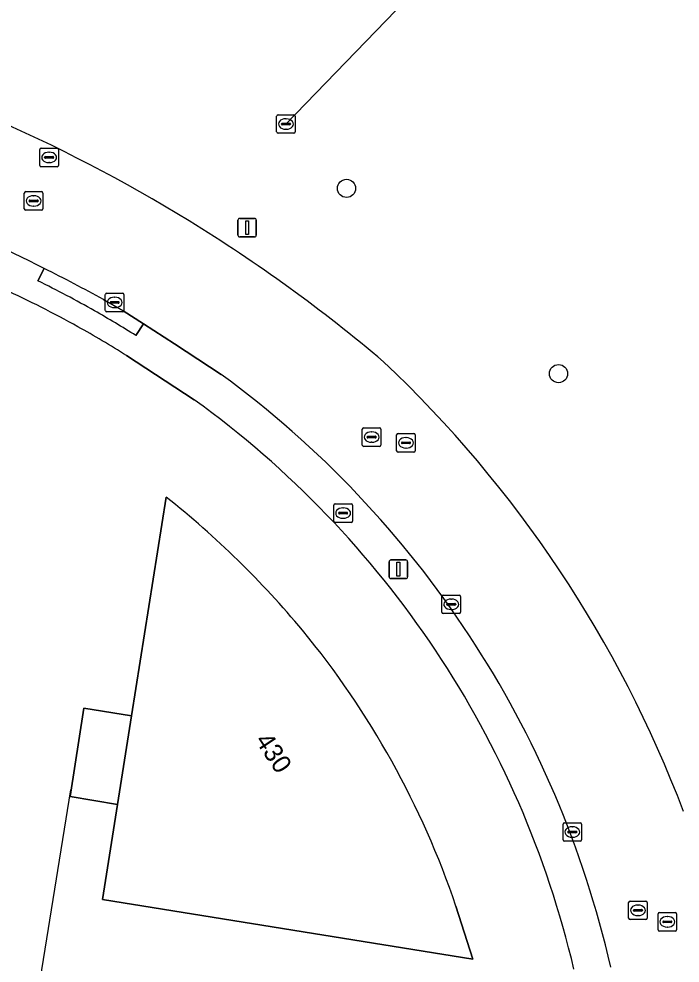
# Model space of a CAD drawing. Extents: x 154324 to 155744, y 382937 to 384188.
# Drawn here: x 155347.8 to 155383.3, y 383421.7 to 383472.5 of the extents above; entities that cross this region are included whole.
import ezdxf

# ---------------------------------------------------------------- set-up
doc = ezdxf.new("R2010")
doc.units = 0
for name, color, linetype in [('IMGEO_Boom', 7, 'Continuous'), ('IMGEO_Brandkraan', 7, 'Continuous'), ('IMGEO_Duiker', 7, 'Continuous'), ('IMGEO_Erf', 7, 'Continuous'), ('IMGEO_Groenvoorziening', 7, 'Continuous'), ('IMGEO_Hek', 7, 'Continuous'), ('IMGEO_Kolk', 7, 'Continuous'), ('IMGEO_Lichtmast', 7, 'Continuous'), ('IMGEO_Pand', 7, 'Continuous'), ('IMGEO_Pand_nummerreeks', 7, 'Continuous'), ('IMGEO_Rijbaan_lokaal_open', 7, 'Continuous'), ('IMGEO_Rioolput', 7, 'Continuous'), ('IMGEO_Voetpad_open', 7, 'Continuous')]:
    doc.layers.add(name, color=color, linetype=linetype)

msp = doc.modelspace()

# ---------------------------------------------------------------- linework, layer by layer
at = {"layer": 'IMGEO_Boom'}
for centre in [(155365.404, 383463.411), (155376.801, 383453.45)]:
    msp.add_circle(centre, 0.489, dxfattribs=at)
at = {"layer": 'IMGEO_Brandkraan'}
for p, q in [((155364.796, 383446.444), (155365.648, 383446.444)), ((155364.721, 383445.518), (155364.721, 383446.37)), ((155364.98, 383445.938), (155364.98, 383445.95)), ((155365.023, 383445.987), (155365.421, 383445.987)), ((155365.209, 383446.224), (155365.234, 383446.224)), ((155365.464, 383445.95), (155365.464, 383445.938)), ((155365.722, 383446.37), (155365.722, 383445.518)), ((155365.648, 383445.444), (155364.796, 383445.444)), ((155365.418, 383445.901), (155365.02, 383445.901)), ((155365.232, 383445.664), (155365.207, 383445.664))]:
    msp.add_line(p, q, dxfattribs=at)
for points in [[(155364.796, 383446.444), (155365.648, 383446.444)], [(155364.721, 383445.518), (155364.721, 383446.37)], [(155365.722, 383446.37), (155365.722, 383445.518)], [(155365.648, 383445.444), (155364.796, 383445.444)]]:
    msp.add_lwpolyline(points, dxfattribs=at)
for centre, radius, start, end in [((155364.798, 383446.368), 0.0765, 91.552, 178.448), ((155364.798, 383446.368), 0.0765, 91.552, 178.448), ((155365.646, 383446.368), 0.0765, 1.552, 88.448), ((155365.646, 383446.368), 0.0765, 1.552, 88.448), ((155365.02, 383445.947), 0.0403, 85.8775, 175.7526), ((155365.017, 383445.937), 0.0366, 178.938, 274.7102), ((155365.421, 383445.944), 0.043, 264.8664, 352.4533), ((155365.425, 383445.949), 0.0386, 1.7309, 96.639), ((155364.798, 383445.52), 0.0765, 181.552, 268.448), ((155364.798, 383445.52), 0.0765, 181.552, 268.448), ((155365.646, 383445.52), 0.0765, 271.552, 358.448), ((155365.646, 383445.52), 0.0765, 271.552, 358.448)]:
    msp.add_arc(centre, radius, start, end, dxfattribs=at)
for centre, major_axis, ratio, start_param, end_param in [((155365.208, 383445.944), (-0.387, 0.002), 0.722429, 4.712389, 7.853982), ((155365.233, 383445.944), (-0.39, 0.002), 0.717154, 1.570796, 4.712389)]:
    msp.add_ellipse(centre, major_axis=major_axis, ratio=ratio, start_param=start_param, end_param=end_param, dxfattribs=at)
at = {"layer": 'IMGEO_Duiker'}
msp.add_lwpolyline([(155362.15, 383466.875), (155370.748, 383475.778)], dxfattribs=at)
at = {"layer": 'IMGEO_Erf'}
for points in [[(155357.216, 383452.045), (155353.569, 383454.42)], [(155352.285, 383425.153), (155353.096, 383430.27), (155350.549, 383430.699), (155351.285, 383435.448), (155353.852, 383435.041), (155355.715, 383446.803)], [(155371.286, 383424.798), (155372.19, 383421.959), (155352.285, 383425.153)]]:
    msp.add_lwpolyline(points, dxfattribs=at)
for centre, radius, start, end in [((155325.371, 383410.082), 52.545, 60.8513, 65.7078), ((155325.24, 383409.862), 52.801, 57.5525, 60.844), ((155326.36, 383409.367), 52.663, 13.2166, 54.1334), ((155325.018, 383408.09), 49.406, 39.6858, 51.5876), ((155326.8, 383409.792), 46.949, 18.6408, 39.4769)]:
    msp.add_arc(centre, radius, start, end, dxfattribs=at)
at = {"layer": 'IMGEO_Groenvoorziening'}
for centre, radius, start, end in [((155312.033, 383388.632), 85.735, 58.41362, 74.83277), ((155311.996, 383388.605), 85.777, 49.76722, 58.40243), ((155322.678, 383406.824), 65.069, 20.763, 46.58434)]:
    msp.add_arc(centre, radius, start, end, dxfattribs=at)
at = {"layer": 'IMGEO_Hek'}
msp.add_lwpolyline([(155353.397, 383415.758), (155348.254, 383416.592), (155350.587, 383431.051)], dxfattribs=at)
at = {"layer": 'IMGEO_Kolk'}
for p, q in [((155352.439, 383456.851), (155352.439, 383457.703)), ((155352.514, 383457.777), (155353.366, 383457.777)), ((155353.44, 383457.703), (155353.44, 383456.851)), ((155352.698, 383457.271), (155352.698, 383457.283)), ((155353.136, 383457.234), (155352.738, 383457.234)), ((155352.741, 383457.32), (155353.139, 383457.32)), ((155352.927, 383457.557), (155352.952, 383457.557)), ((155353.182, 383457.283), (155353.182, 383457.271)), ((155353.366, 383456.777), (155352.514, 383456.777)), ((155352.95, 383456.997), (155352.925, 383456.997)), ((155370.531, 383440.613), (155370.531, 383441.465)), ((155370.606, 383441.539), (155371.458, 383441.539)), ((155371.532, 383441.465), (155371.532, 383440.613)), ((155370.79, 383441.033), (155370.79, 383441.045)), ((155371.228, 383440.996), (155370.83, 383440.996)), ((155370.833, 383441.082), (155371.231, 383441.082)), ((155371.019, 383441.319), (155371.044, 383441.319)), ((155371.274, 383441.045), (155371.274, 383441.033)), ((155371.458, 383440.539), (155370.606, 383440.539)), ((155371.042, 383440.759), (155371.017, 383440.759)), ((155377.041, 383428.365), (155377.041, 383429.217)), ((155377.116, 383429.291), (155377.968, 383429.291)), ((155378.042, 383429.217), (155378.042, 383428.365)), ((155377.3, 383428.785), (155377.3, 383428.797)), ((155377.738, 383428.748), (155377.34, 383428.748)), ((155377.343, 383428.834), (155377.741, 383428.834)), ((155377.529, 383429.071), (155377.554, 383429.071)), ((155377.784, 383428.797), (155377.784, 383428.785)), ((155377.968, 383428.291), (155377.116, 383428.291)), ((155377.552, 383428.511), (155377.527, 383428.511))]:
    msp.add_line(p, q, dxfattribs=at)
for points in [[(155352.439, 383456.851), (155352.439, 383457.703)], [(155352.514, 383457.777), (155353.366, 383457.777)], [(155353.44, 383457.703), (155353.44, 383456.851)], [(155353.366, 383456.777), (155352.514, 383456.777)], [(155370.531, 383440.613), (155370.531, 383441.465)], [(155370.606, 383441.539), (155371.458, 383441.539)], [(155371.532, 383441.465), (155371.532, 383440.613)], [(155371.458, 383440.539), (155370.606, 383440.539)], [(155377.041, 383428.365), (155377.041, 383429.217)], [(155377.116, 383429.291), (155377.968, 383429.291)], [(155378.042, 383429.217), (155378.042, 383428.365)], [(155377.968, 383428.291), (155377.116, 383428.291)]]:
    msp.add_lwpolyline(points, dxfattribs=at)
for centre, radius, start, end in [((155352.516, 383457.701), 0.0765, 91.552, 178.448), ((155352.516, 383457.701), 0.0765, 91.552, 178.448), ((155353.364, 383457.701), 0.0765, 1.552, 88.448), ((155353.364, 383457.701), 0.0765, 1.552, 88.448), ((155352.738, 383457.28), 0.0403, 85.8775, 175.7526), ((155352.735, 383457.27), 0.0366, 178.938, 274.7102), ((155353.139, 383457.277), 0.043, 264.8664, 352.4533), ((155353.143, 383457.282), 0.0386, 1.7309, 96.639), ((155352.516, 383456.853), 0.0765, 181.552, 268.448), ((155352.516, 383456.853), 0.0765, 181.552, 268.448), ((155353.364, 383456.853), 0.0765, 271.552, 358.448), ((155353.364, 383456.853), 0.0765, 271.552, 358.448), ((155370.608, 383441.463), 0.0765, 91.552, 178.448), ((155370.608, 383441.463), 0.0765, 91.552, 178.448), ((155371.456, 383441.463), 0.0765, 1.552, 88.448), ((155371.456, 383441.463), 0.0765, 1.552, 88.448), ((155370.83, 383441.042), 0.0403, 85.8775, 175.7526), ((155370.827, 383441.032), 0.0366, 178.938, 274.7102), ((155371.231, 383441.039), 0.043, 264.8664, 352.4533), ((155371.235, 383441.044), 0.0386, 1.7309, 96.639), ((155370.608, 383440.615), 0.0765, 181.552, 268.448), ((155370.608, 383440.615), 0.0765, 181.552, 268.448), ((155371.456, 383440.615), 0.0765, 271.552, 358.448), ((155371.456, 383440.615), 0.0765, 271.552, 358.448), ((155377.118, 383429.215), 0.0765, 91.552, 178.448), ((155377.118, 383429.215), 0.0765, 91.552, 178.448), ((155377.966, 383429.215), 0.0765, 1.552, 88.448), ((155377.966, 383429.215), 0.0765, 1.552, 88.448), ((155377.34, 383428.794), 0.0403, 85.8775, 175.7526), ((155377.337, 383428.784), 0.0366, 178.938, 274.7102), ((155377.741, 383428.791), 0.043, 264.8664, 352.4533), ((155377.745, 383428.796), 0.0386, 1.7309, 96.639), ((155377.118, 383428.367), 0.0765, 181.552, 268.448), ((155377.118, 383428.367), 0.0765, 181.552, 268.448), ((155377.966, 383428.367), 0.0765, 271.552, 358.448), ((155377.966, 383428.367), 0.0765, 271.552, 358.448)]:
    msp.add_arc(centre, radius, start, end, dxfattribs=at)
for centre, major_axis, ratio, start_param, end_param in [((155352.926, 383457.277), (-0.387, 0.002), 0.722429, 4.712389, 7.853982), ((155352.951, 383457.277), (-0.39, 0.002), 0.717154, 1.570796, 4.712389), ((155371.018, 383441.039), (-0.387, 0.002), 0.722429, 4.712389, 7.853982), ((155371.043, 383441.039), (-0.39, 0.002), 0.717154, 1.570796, 4.712389), ((155377.528, 383428.791), (-0.387, 0.002), 0.722429, 4.712389, 7.853982), ((155377.553, 383428.791), (-0.39, 0.002), 0.717154, 1.570796, 4.712389)]:
    msp.add_ellipse(centre, major_axis=major_axis, ratio=ratio, start_param=start_param, end_param=end_param, dxfattribs=at)
at = {"layer": 'IMGEO_Lichtmast'}
for p, q in [((155359.563, 383460.901), (155359.563, 383461.701)), ((155359.563, 383461.701), (155359.563, 383460.901)), ((155359.663, 383461.801), (155360.453, 383461.801)), ((155360.453, 383461.801), (155359.663, 383461.801)), ((155360.553, 383461.701), (155360.553, 383460.901)), ((155360.553, 383460.901), (155360.553, 383461.701)), ((155360.453, 383460.801), (155359.663, 383460.801)), ((155359.663, 383460.801), (155360.453, 383460.801)), ((155367.795, 383443.423), (155368.585, 383443.423)), ((155368.585, 383443.423), (155367.795, 383443.423)), ((155367.695, 383442.523), (155367.695, 383443.323)), ((155367.695, 383443.323), (155367.695, 383442.523)), ((155368.685, 383443.323), (155368.685, 383442.523)), ((155368.685, 383442.523), (155368.685, 383443.323)), ((155368.585, 383442.423), (155367.795, 383442.423)), ((155367.795, 383442.423), (155368.585, 383442.423))]:
    msp.add_line(p, q, dxfattribs=at)
for points in [[(155359.983, 383461.676), (155360.133, 383461.676), (155360.133, 383460.926), (155359.983, 383460.926), (155359.983, 383461.676)], [(155368.115, 383443.298), (155368.265, 383443.298), (155368.265, 383442.548), (155368.115, 383442.548), (155368.115, 383443.298)]]:
    msp.add_lwpolyline(points, dxfattribs=at)
for centre, start, end in [((155359.663, 383461.701), 90, 180), ((155359.663, 383461.701), 90, 180), ((155360.453, 383461.701), 0, 90), ((155360.453, 383461.701), 360, 90), ((155359.663, 383460.901), 180, 270), ((155359.663, 383460.901), 180, 270), ((155360.453, 383460.901), 270, 0), ((155360.453, 383460.901), 270, 0), ((155367.795, 383443.323), 90, 180), ((155367.795, 383443.323), 90, 180), ((155368.585, 383443.323), 0, 90), ((155368.585, 383443.323), 360, 90), ((155367.795, 383442.523), 180, 270), ((155367.795, 383442.523), 180, 270), ((155368.585, 383442.523), 270, 0), ((155368.585, 383442.523), 270, 0)]:
    msp.add_arc(centre, 0.1, start, end, dxfattribs=at)
at = {"layer": 'IMGEO_Pand'}
msp.add_lwpolyline([(155355.715, 383446.803), (155353.852, 383435.041), (155353.096, 383430.27), (155352.285, 383425.153), (155372.19, 383421.959), (155371.286, 383424.798)], dxfattribs=at)
msp.add_lwpolyline([(155353.852, 383435.041), (155351.285, 383435.448), (155350.549, 383430.699), (155353.096, 383430.27)], close=True, dxfattribs=at)
for centre, radius, start, end in [((155325.018, 383408.09), 49.406, 39.6858, 51.5876), ((155326.8, 383409.792), 46.949, 18.6408, 39.4769)]:
    msp.add_arc(centre, radius, start, end, dxfattribs=at)
at = {"layer": 'IMGEO_Rijbaan_lokaal_open'}
msp.add_lwpolyline([(155352.346, 383457.432), (155352.439, 383457.379), (155353.405, 383456.833), (155354.49, 383456.132), (155356.158, 383455.053), (155358.672, 383453.408)], dxfattribs=at)
for centre, radius, start, end in [((155312.033, 383388.632), 85.735, 58.41362, 74.83277), ((155302.55, 383366.417), 103.746, 63.30392, 67.32185), ((155311.996, 383388.605), 85.777, 49.76722, 58.40243), ((155303.395, 383367.999), 101.953, 61.30576, 63.32842), ((155322.678, 383406.824), 65.069, 20.763, 46.58434), ((155326.335, 383409.358), 54.645, 12.8574, 53.718)]:
    msp.add_arc(centre, radius, start, end, dxfattribs=at)
at = {"layer": 'IMGEO_Rioolput'}
for p, q in [((155361.649, 383466.449), (155361.649, 383467.301)), ((155361.724, 383467.375), (155362.576, 383467.375)), ((155362.65, 383467.301), (155362.65, 383466.449)), ((155361.908, 383466.869), (155361.908, 383466.881)), ((155362.346, 383466.832), (155361.948, 383466.832)), ((155361.951, 383466.918), (155362.349, 383466.918)), ((155362.137, 383467.155), (155362.162, 383467.155)), ((155362.392, 383466.881), (155362.392, 383466.869)), ((155362.576, 383466.375), (155361.724, 383466.375)), ((155362.16, 383466.595), (155362.135, 383466.595)), ((155348.918, 383464.652), (155348.918, 383465.504)), ((155348.993, 383465.578), (155349.845, 383465.578)), ((155349.406, 383465.358), (155349.431, 383465.358)), ((155349.919, 383465.504), (155349.919, 383464.652)), ((155349.177, 383465.072), (155349.177, 383465.084)), ((155349.615, 383465.035), (155349.217, 383465.035)), ((155349.22, 383465.121), (155349.618, 383465.121)), ((155349.429, 383464.798), (155349.404, 383464.798)), ((155349.661, 383465.084), (155349.661, 383465.072)), ((155349.845, 383464.578), (155348.993, 383464.578)), ((155348.159, 383463.238), (155349.011, 383463.238)), ((155348.084, 383462.312), (155348.084, 383463.164)), ((155348.343, 383462.732), (155348.343, 383462.744)), ((155348.781, 383462.695), (155348.383, 383462.695)), ((155348.386, 383462.781), (155348.784, 383462.781)), ((155348.572, 383463.018), (155348.597, 383463.018)), ((155348.827, 383462.744), (155348.827, 383462.732)), ((155349.085, 383463.164), (155349.085, 383462.312)), ((155349.011, 383462.238), (155348.159, 383462.238)), ((155348.595, 383462.458), (155348.57, 383462.458)), ((155366.326, 383450.534), (155367.178, 383450.534)), ((155366.251, 383449.608), (155366.251, 383450.46)), ((155366.51, 383450.028), (155366.51, 383450.04)), ((155366.553, 383450.077), (155366.951, 383450.077)), ((155366.739, 383450.314), (155366.764, 383450.314)), ((155366.994, 383450.04), (155366.994, 383450.028)), ((155367.252, 383450.46), (155367.252, 383449.608)), ((155368.099, 383449.299), (155368.099, 383450.151)), ((155368.174, 383450.225), (155369.026, 383450.225)), ((155368.587, 383450.005), (155368.612, 383450.005)), ((155369.1, 383450.151), (155369.1, 383449.299)), ((155367.178, 383449.534), (155366.326, 383449.534)), ((155366.948, 383449.991), (155366.55, 383449.991)), ((155366.762, 383449.754), (155366.737, 383449.754)), ((155368.358, 383449.719), (155368.358, 383449.731)), ((155368.796, 383449.682), (155368.398, 383449.682)), ((155368.401, 383449.768), (155368.799, 383449.768)), ((155368.842, 383449.731), (155368.842, 383449.719)), ((155369.026, 383449.225), (155368.174, 383449.225)), ((155368.61, 383449.445), (155368.585, 383449.445)), ((155380.57, 383424.152), (155380.57, 383425.004)), ((155380.645, 383425.078), (155381.497, 383425.078)), ((155380.872, 383424.621), (155381.27, 383424.621)), ((155381.058, 383424.858), (155381.083, 383424.858)), ((155381.571, 383425.004), (155381.571, 383424.152)), ((155380.829, 383424.572), (155380.829, 383424.584)), ((155381.267, 383424.535), (155380.869, 383424.535)), ((155381.081, 383424.298), (155381.056, 383424.298)), ((155381.313, 383424.584), (155381.313, 383424.572)), ((155382.149, 383423.534), (155382.149, 383424.386)), ((155382.224, 383424.46), (155383.076, 383424.46)), ((155382.637, 383424.24), (155382.662, 383424.24)), ((155383.15, 383424.386), (155383.15, 383423.534)), ((155381.497, 383424.078), (155380.645, 383424.078)), ((155382.408, 383423.954), (155382.408, 383423.966)), ((155382.846, 383423.917), (155382.448, 383423.917)), ((155382.451, 383424.003), (155382.849, 383424.003)), ((155382.66, 383423.68), (155382.635, 383423.68)), ((155382.892, 383423.966), (155382.892, 383423.954)), ((155383.076, 383423.46), (155382.224, 383423.46))]:
    msp.add_line(p, q, dxfattribs=at)
for points in [[(155361.649, 383466.449), (155361.649, 383467.301)], [(155361.724, 383467.375), (155362.576, 383467.375)], [(155362.65, 383467.301), (155362.65, 383466.449)], [(155362.576, 383466.375), (155361.724, 383466.375)], [(155348.918, 383464.652), (155348.918, 383465.504)], [(155348.993, 383465.578), (155349.845, 383465.578)], [(155349.919, 383465.504), (155349.919, 383464.652)], [(155349.845, 383464.578), (155348.993, 383464.578)], [(155348.159, 383463.238), (155349.011, 383463.238)], [(155348.084, 383462.312), (155348.084, 383463.164)], [(155349.085, 383463.164), (155349.085, 383462.312)], [(155349.011, 383462.238), (155348.159, 383462.238)], [(155366.326, 383450.534), (155367.178, 383450.534)], [(155366.251, 383449.608), (155366.251, 383450.46)], [(155367.252, 383450.46), (155367.252, 383449.608)], [(155368.099, 383449.299), (155368.099, 383450.151)], [(155368.174, 383450.225), (155369.026, 383450.225)], [(155369.1, 383450.151), (155369.1, 383449.299)], [(155367.178, 383449.534), (155366.326, 383449.534)], [(155369.026, 383449.225), (155368.174, 383449.225)], [(155380.57, 383424.152), (155380.57, 383425.004)], [(155380.645, 383425.078), (155381.497, 383425.078)], [(155381.571, 383425.004), (155381.571, 383424.152)], [(155382.149, 383423.534), (155382.149, 383424.386)], [(155382.224, 383424.46), (155383.076, 383424.46)], [(155383.15, 383424.386), (155383.15, 383423.534)], [(155381.497, 383424.078), (155380.645, 383424.078)], [(155383.076, 383423.46), (155382.224, 383423.46)]]:
    msp.add_lwpolyline(points, dxfattribs=at)
for centre, radius, start, end in [((155361.726, 383467.299), 0.0765, 91.552, 178.448), ((155361.726, 383467.299), 0.0765, 91.552, 178.448), ((155362.574, 383467.299), 0.0765, 1.552, 88.448), ((155362.574, 383467.299), 0.0765, 1.552, 88.448), ((155361.948, 383466.878), 0.0403, 85.8775, 175.7526), ((155361.945, 383466.868), 0.0366, 178.938, 274.7102), ((155362.349, 383466.875), 0.043, 264.8664, 352.4533), ((155362.353, 383466.88), 0.0386, 1.7309, 96.639), ((155361.726, 383466.451), 0.0765, 181.552, 268.448), ((155361.726, 383466.451), 0.0765, 181.552, 268.448), ((155362.574, 383466.451), 0.0765, 271.552, 358.448), ((155362.574, 383466.451), 0.0765, 271.552, 358.448), ((155348.995, 383465.502), 0.0765, 91.552, 178.448), ((155348.995, 383465.502), 0.0765, 91.552, 178.448), ((155349.843, 383465.502), 0.0765, 1.552, 88.448), ((155349.843, 383465.502), 0.0765, 1.552, 88.448), ((155349.217, 383465.081), 0.0403, 85.8775, 175.7526), ((155349.214, 383465.071), 0.0366, 178.938, 274.7102), ((155349.618, 383465.078), 0.043, 264.8664, 352.4533), ((155349.622, 383465.083), 0.0386, 1.7309, 96.639), ((155348.995, 383464.654), 0.0765, 181.552, 268.448), ((155348.995, 383464.654), 0.0765, 181.552, 268.448), ((155349.843, 383464.654), 0.0765, 271.552, 358.448), ((155349.843, 383464.654), 0.0765, 271.552, 358.448), ((155348.161, 383463.162), 0.0765, 91.552, 178.448), ((155348.161, 383463.162), 0.0765, 91.552, 178.448), ((155349.009, 383463.162), 0.0765, 1.552, 88.448), ((155349.009, 383463.162), 0.0765, 1.552, 88.448), ((155348.383, 383462.741), 0.0403, 85.8775, 175.7526), ((155348.38, 383462.731), 0.0366, 178.938, 274.7102), ((155348.784, 383462.738), 0.043, 264.8664, 352.4533), ((155348.788, 383462.743), 0.0386, 1.7309, 96.639), ((155348.161, 383462.314), 0.0765, 181.552, 268.448), ((155348.161, 383462.314), 0.0765, 181.552, 268.448), ((155349.009, 383462.314), 0.0765, 271.552, 358.448), ((155349.009, 383462.314), 0.0765, 271.552, 358.448), ((155366.328, 383450.458), 0.0765, 91.552, 178.448), ((155366.328, 383450.458), 0.0765, 91.552, 178.448), ((155367.176, 383450.458), 0.0765, 1.552, 88.448), ((155367.176, 383450.458), 0.0765, 1.552, 88.448), ((155366.55, 383450.037), 0.0403, 85.8775, 175.7526), ((155366.547, 383450.027), 0.0366, 178.938, 274.7102), ((155366.951, 383450.034), 0.043, 264.8664, 352.4533), ((155366.955, 383450.039), 0.0386, 1.7309, 96.639), ((155368.176, 383450.149), 0.0765, 91.552, 178.448), ((155368.176, 383450.149), 0.0765, 91.552, 178.448), ((155369.024, 383450.149), 0.0765, 1.552, 88.448), ((155369.024, 383450.149), 0.0765, 1.552, 88.448), ((155366.328, 383449.61), 0.0765, 181.552, 268.448), ((155366.328, 383449.61), 0.0765, 181.552, 268.448), ((155367.176, 383449.61), 0.0765, 271.552, 358.448), ((155367.176, 383449.61), 0.0765, 271.552, 358.448), ((155368.398, 383449.728), 0.0403, 85.8775, 175.7526), ((155368.395, 383449.718), 0.0366, 178.938, 274.7102), ((155368.799, 383449.725), 0.043, 264.8664, 352.4533), ((155368.803, 383449.73), 0.0386, 1.7309, 96.639), ((155368.176, 383449.301), 0.0765, 181.552, 268.448), ((155368.176, 383449.301), 0.0765, 181.552, 268.448), ((155369.024, 383449.301), 0.0765, 271.552, 358.448), ((155369.024, 383449.301), 0.0765, 271.552, 358.448), ((155380.647, 383425.002), 0.0765, 91.552, 178.448), ((155380.647, 383425.002), 0.0765, 91.552, 178.448), ((155380.869, 383424.581), 0.0403, 85.8775, 175.7526), ((155381.274, 383424.583), 0.0386, 1.7309, 96.639), ((155381.495, 383425.002), 0.0765, 1.552, 88.448), ((155381.495, 383425.002), 0.0765, 1.552, 88.448), ((155380.647, 383424.154), 0.0765, 181.552, 268.448), ((155380.647, 383424.154), 0.0765, 181.552, 268.448), ((155380.866, 383424.571), 0.0366, 178.938, 274.7102), ((155381.27, 383424.578), 0.043, 264.8664, 352.4533), ((155381.495, 383424.154), 0.0765, 271.552, 358.448), ((155381.495, 383424.154), 0.0765, 271.552, 358.448), ((155382.226, 383424.384), 0.0765, 91.552, 178.448), ((155382.226, 383424.384), 0.0765, 91.552, 178.448), ((155383.074, 383424.384), 0.0765, 1.552, 88.448), ((155383.074, 383424.384), 0.0765, 1.552, 88.448), ((155382.448, 383423.963), 0.0403, 85.8775, 175.7526), ((155382.445, 383423.953), 0.0366, 178.938, 274.7102), ((155382.849, 383423.96), 0.043, 264.8664, 352.4533), ((155382.853, 383423.965), 0.0386, 1.7309, 96.639), ((155382.226, 383423.536), 0.0765, 181.552, 268.448), ((155382.226, 383423.536), 0.0765, 181.552, 268.448), ((155383.074, 383423.536), 0.0765, 271.552, 358.448), ((155383.074, 383423.536), 0.0765, 271.552, 358.448)]:
    msp.add_arc(centre, radius, start, end, dxfattribs=at)
for centre, major_axis, ratio, start_param, end_param in [((155362.136, 383466.875), (-0.387, 0.002), 0.722429, 4.712389, 7.853982), ((155362.161, 383466.875), (-0.39, 0.002), 0.717154, 1.570796, 4.712389), ((155349.405, 383465.078), (-0.387, 0.002), 0.722429, 4.712389, 7.853982), ((155349.43, 383465.078), (-0.39, 0.002), 0.717154, 1.570796, 4.712389), ((155348.571, 383462.738), (-0.387, 0.002), 0.722429, 4.712389, 7.853982), ((155348.596, 383462.738), (-0.39, 0.002), 0.717154, 1.570796, 4.712389), ((155366.738, 383450.034), (-0.387, 0.002), 0.722429, 4.712389, 7.853982), ((155366.763, 383450.034), (-0.39, 0.002), 0.717154, 1.570796, 4.712389), ((155368.586, 383449.725), (-0.387, 0.002), 0.722429, 4.712389, 7.853982), ((155368.611, 383449.725), (-0.39, 0.002), 0.717154, 1.570796, 4.712389), ((155381.057, 383424.578), (-0.387, 0.002), 0.722429, 4.712389, 7.853982), ((155381.082, 383424.578), (-0.39, 0.002), 0.717154, 1.570796, 4.712389), ((155382.636, 383423.96), (-0.387, 0.002), 0.722429, 4.712389, 7.853982), ((155382.661, 383423.96), (-0.39, 0.002), 0.717154, 1.570796, 4.712389)]:
    msp.add_ellipse(centre, major_axis=major_axis, ratio=ratio, start_param=start_param, end_param=end_param, dxfattribs=at)
at = {"layer": 'IMGEO_Voetpad_open'}
for points in [[(155349.159, 383459.104), (155348.816, 383458.437)], [(155348.816, 383458.437), (155349.159, 383459.104)], [(155354.081, 383455.494), (155354.49, 383456.132), (155353.405, 383456.833), (155352.439, 383457.379), (155352.346, 383457.432)], [(155358.672, 383453.408), (155356.158, 383455.053), (155354.49, 383456.132), (155354.081, 383455.494)], [(155353.569, 383454.42), (155357.216, 383452.045)]]:
    msp.add_lwpolyline(points, dxfattribs=at)
for centre, radius, start, end in [((155302.55, 383366.417), 103.746, 63.30392, 67.32185), ((155303.395, 383367.999), 101.953, 61.30576, 63.32842), ((155324.295, 383408.44), 55.687, 60.3311, 63.8743), ((155324.295, 383408.44), 55.687, 60.3311, 63.8743), ((155325.371, 383410.082), 52.545, 60.8513, 65.7078), ((155324.714, 383409.024), 54.972, 57.7088, 60.4092), ((155324.714, 383409.024), 54.972, 57.7088, 60.4092), ((155325.24, 383409.862), 52.801, 57.5525, 60.844), ((155326.335, 383409.358), 54.645, 12.8574, 53.718), ((155326.36, 383409.367), 52.663, 13.2166, 54.1334)]:
    msp.add_arc(centre, radius, start, end, dxfattribs=at)

# ---------------------------------------------------------------- texts
at = {"layer": 'IMGEO_Pand_nummerreeks'}
msp.add_text('430', height=1, rotation=303.5522, dxfattribs=at).set_placement((155360.46, 383433.712))

doc.saveas('drawing.dxf')
